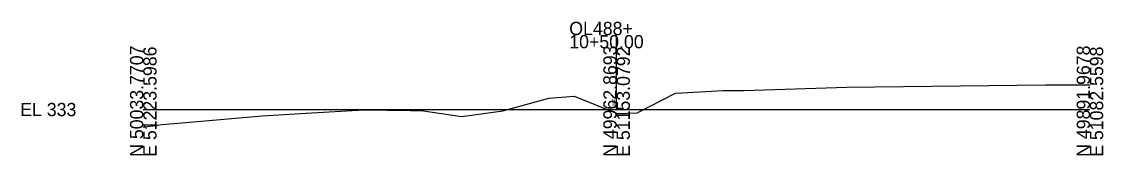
# Model space of a CAD drawing. Extents: x 6002 to 6231, y 90221 to 94244.
# Drawn here: x 6002 to 6230.5, y 90721.3 to 90749.6 of the extents above; entities that cross this region are included whole.
import ezdxf

# ---------------------------------------------------------------- set-up
doc = ezdxf.new("R2010")
doc.units = 0
for name, color, linetype in [('Level 10', 7, 'Continuous'), ('Level 60', 7, 'Continuous'), ('Level 63', 7, 'Continuous')]:
    doc.layers.add(name, color=color, linetype=linetype)

msp = doc.modelspace()

# ---------------------------------------------------------------- linework, layer by layer
at = {"layer": 'Level 60'}
for p, q in [((6141.46, 90734.52), (6150.19, 90734.96)), ((6150.19, 90734.96), (6154.57, 90735.01)), ((6154.57, 90735.01), (6176.3, 90735.69)), ((6176.3, 90735.69), (6218.25, 90736.21)), ((6218.25, 90736.21), (6227.67, 90736.22)), ((6103.65, 90730.71), (6113.34, 90733.36)), ((6113.34, 90733.36), (6118.71, 90733.76)), ((6118.71, 90733.76), (6127.79, 90730.13)), ((6132.02, 90730.26), (6140.12, 90734.46)), ((6140.12, 90734.46), (6141.46, 90734.52)), ((6062.08, 90730.17), (6074.26, 90730.92)), ((6074.26, 90730.92), (6084.08, 90730.78)), ((6084.08, 90730.78), (6086.36, 90730.79)), ((6086.36, 90730.79), (6094.99, 90729.51)), ((6095.44, 90729.57), (6103.65, 90730.71)), ((6031.57, 90727.77), (6036.66, 90728.22)), ((6036.66, 90728.22), (6052.77, 90729.61)), ((6052.77, 90729.61), (6062.08, 90730.17)), ((6094.99, 90729.51), (6095.44, 90729.57)), ((6127.79, 90730.13), (6132.02, 90730.26)), ((6027.67, 90727.23), (6030.7, 90727.65)), ((6030.7, 90727.65), (6031.57, 90727.77))]:
    msp.add_line(p, q, dxfattribs=at)
at = {"layer": 'Level 63'}
for p, q in [((6127.67, 90730.97), (6127.67, 90746.71)), ((6027.67, 90730.97), (6127.67, 90730.97)), ((6127.67, 90730.97), (6227.67, 90730.97))]:
    msp.add_line(p, q, dxfattribs=at)

# ---------------------------------------------------------------- texts
at = {"layer": 'Level 10'}
msp.add_text('332.21', height=0.6, rotation=90, dxfattribs=at).set_placement((6127.27, 90731.18))
at = {"layer": 'Level 63'}
for s, p in [('OL488+', (6117.67, 90746.71)), ('10+50.00', (6117.67, 90743.91)), ('EL 333', (6001.67, 90729.57))]:
    msp.add_text(s, height=2.8, dxfattribs=at).set_placement(p)
for s, p in [('N 50033.7707', (6027.67, 90720.97)), ('E 51223.5986', (6030.47, 90720.97)), ('N 49962.8693', (6127.67, 90720.97)), ('E 51153.0792', (6130.47, 90720.97)), ('N 49891.9678', (6227.67, 90720.97)), ('E 51082.5598', (6230.47, 90720.97))]:
    msp.add_text(s, height=2.8, rotation=90, dxfattribs=at).set_placement(p)

doc.saveas('drawing.dxf')
